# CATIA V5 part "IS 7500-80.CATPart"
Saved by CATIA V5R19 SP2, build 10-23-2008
Part number: IS 7500-80
Bounding box of the stored display mesh (mm): x -74.81 to 74.81, y -74.81 to 74.81, z 0 to 315
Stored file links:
  C:\Users\Bora\Desktop\3D Katı model\IS serisi\IS 7500\IS 7500-80.CATPart
  C:\Program Files\Dassault Systemes\B19\intel_a\reffiles\standard\MetricThickPitch.txt
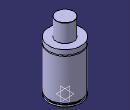
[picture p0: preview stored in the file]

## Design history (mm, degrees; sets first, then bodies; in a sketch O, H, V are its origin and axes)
Body1 (main body)
  Sketch1 on yz-plane, origin (0, 0, 0), H (0, 1, 0), V (0, 0, 1)
    point P1 (75, 210)
    point P2 (75, 205)
    point P5 (40, 314)
    point P7 (40, 314)
    point P12 (75, 205)
    point P13 (75, 210)
    arc A1 centre (75, 207.5) radius 2.5 from (75, 210) to (75, 205) ccw
    line L1 (75, 0) -> (75, 8)
    line L2 (40, 314) -> (40, 232)
    arc A2 centre (39, 314) radius 1 from (40, 314) to (39, 315) ccw
    line L3 (71, 15) -> (71, 8)
    line L4 (75, 15) -> (75, 205)
    line L5 (75, 210) -> (75, 232)
    line L6 (39, 315) -> (0, 315)
    point P15 (0, 315)
    line L7 (40, 232) -> (75, 232)
    line L8 (0, 0) -> (75, 0)
    line L9 (71, 15) -> (75, 15)
    line L10 (71, 8) -> (75, 8)
    coincidence: P15 V, P1 P13, P2 P12, P5 P7
    tangency: L6 A2
    horizontal: L7 H, L8 H, L9 H, L10 H
  Shaft1: profile Sketch1, axis Sketch1.V, angle 360
  Sketch2 on face of Shaft1 from Sketch1.L8, origin (0, 0, 0), H (1, 0, 0), V (0, -1, 0)
    point P1 (50, 0)
    distance V P1 = 50
  Hole1: placed by Sketch2, at (50, 0, 0) direction (0, 0, 1), diameter 8.376, depth 16, threaded "M10", thread diameter 10, thread depth 16, pitch 1.5
  CircPattern1: of Hole1, instances 4, angular step 90, axis from xy-plane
